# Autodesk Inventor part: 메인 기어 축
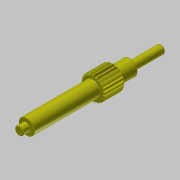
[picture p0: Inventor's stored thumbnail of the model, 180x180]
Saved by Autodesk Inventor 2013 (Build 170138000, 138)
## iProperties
Created: 2018-12
Part Number: 메인 기어 축
Material: 강철, 연강
Document SubType Name: Modeling
Designer: mduedu
Categories: <?xml version="1.0" encoding="UTF-16"?> <MemberInstance><Categories><FamilyTemplate><FamilyTemplateParameter ValueType="xs:double" Id="1" ObjectReferenceKey="da
Density: 7.86 g/cm^3
Mass: 179.676 g
Surface Area: 75.4119 cm^2
Volume: 22.8595 cm^3
CustomPartVersion: 1
Author: mduedu
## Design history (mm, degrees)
sketch "Sketch1"
  geometry: C1 r 11.3 at (0, 0)
  constraints: 1 centre point
  dimensions: "d0" = 22.6 diameter of C1 (= da_da)
extrude "Extrusion1" new body sketch "Sketch1" distance "d1" = 20 (= da_b); taper "d2" = 0 deg
workplane "Work Plane2"
sketch "Sketch2"
  geometry: C1 r 11.3 at (0, 0) reference; C2 r 10.5 at (0, 0)
  constraints: 1 centre point, 1 coincident
  dimensions: "d3" = 21 diameter of C2 (= da_dw)
feature "피치 지름" sketch "Sketch2" dims "d4" = 10, "d5" = 0
workplane "Work Plane8"
workplane "Work Plane9"
chamfer "모따기1" distance "d49" = 1; stored, may be unused: second distance "d50" = 2, angle "d51" = 45 deg
sketch "스케치3"
  geometry: C1 r 7.5 at (0, 0); 1 further point
  constraints: 1 centre point, 1 coincident
  dimensions: "d52" = 15 diameter of C1
extrude "돌출2" join sketch "스케치3" distance "d53" = 64; taper "d54" = 0 deg
sketch "스케치4"
  geometry: C1 r 4 at (0, 0); 1 further point
  constraints: 1 centre point, 1 coincident
  dimensions: "d55" = 8 diameter of C1
extrude "돌출3" join sketch "스케치4" distance "d56" = 7; taper "d57" = 0 deg
sketch "스케치5"
  geometry: C1 r 7.5 at (0, 0) reference; C2 r 7.5 at (0, 0) reference; 1 further point
extrude "돌출4" join sketch "스케치5" distance "d58" = 16; taper "d59" = 0 deg
sketch "스케치6"
  geometry: C1 r 4 at (0, 0); 1 further point
  constraints: 1 centre point, 1 coincident
  dimensions: "d60" = 8 diameter of C1
extrude "돌출5" join sketch "스케치6" distance "d61" = 30; taper "d62" = 0 deg
chamfer "모따기2" distance "d63" = 0.5; stored, may be unused: second distance "d64" = 2, angle "d65" = 45 deg
fillet "모깎기1" dims "d66" = 0.5
feature "스퍼 기어" dims "da_b" = 20, "da_d" = 21, "da_aw" = 31, "da_da" = 22.6, "da_df" = 19.086, "da_dw" = 21, angle "da_beta" = 0 deg, "da_lefttooth" = 0, "da_righttooth" = 0
sketch "스케치7" dims "d67" = 18
  geometry: C1 r 0.25 at (0, -9); 2 further points
  constraints: 2 vertical alignment, 1 centre point, 1 coincident, 2 other
  dimensions: "d68" = 0.5 diameter of C1
extrude "돌출6" join sketch "스케치7" distance "d69" = 0.3; taper "d70" = 0 deg
body "Solid1"
body "Srf1"
node "투영된 루프1"
other parameters: "d16" = 31 (= da_aw), "d17" = 0, "d34" = 1.496 (computed from da_z), "d39" = 0, "d41" = 0, "d43" = 31 (= da_aw), "d46" = 31 (= da_aw), "d47" = 0, "d48" = 0
